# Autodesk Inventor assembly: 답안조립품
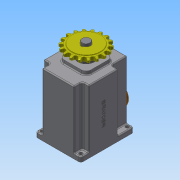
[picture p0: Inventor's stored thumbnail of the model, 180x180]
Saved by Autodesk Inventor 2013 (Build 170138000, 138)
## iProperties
Created: 2017-12
Part Number: 답안조립품
Document SubType Name: Assembly
Designer: Administrator
Author: Administrator
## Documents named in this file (17)
- C:\Users\Administrator\Desktop\371208V1026\답안조립품.iam
- C:\Users\Administrator\Desktop\371208V1026\가변스프링.ipt
- C:\Users\Administrator\Desktop\371208V1026\멈춤나사 M3x8.ipt
- C:\Users\Administrator\Desktop\371208V1026\메인축.ipt
- C:\Users\Administrator\Desktop\371208V1026\베어링 608.ipt
- C:\Users\Administrator\Desktop\371208V1026\베어링 6003.ipt
- C:\Users\Administrator\Desktop\371208V1026\본체.ipt
- C:\Users\Administrator\Desktop\371208V1026\볼트 M4 x 10.ipt
- C:\Users\Administrator\Desktop\371208V1026\부시.ipt
- C:\Users\Administrator\Desktop\371208V1026\상부 캡.ipt
- C:\Users\Administrator\Desktop\371208V1026\서브축.ipt
- C:\Users\Administrator\Desktop\371208V1026\스프로킷.ipt
- C:\Users\Administrator\Desktop\371208V1026\슬라이더.ipt
- C:\Users\Administrator\Desktop\371208V1026\오일 실 8 22 7.ipt
- C:\Users\Administrator\Desktop\371208V1026\오일 실 17 32 8.ipt
- C:\Users\Administrator\Desktop\371208V1026\커버.ipt
- C:\Users\Administrator\Desktop\371208V1026\키 5 x 5 x 18.ipt
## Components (1 placed, 1 different names)
1. 가변스프링:1
